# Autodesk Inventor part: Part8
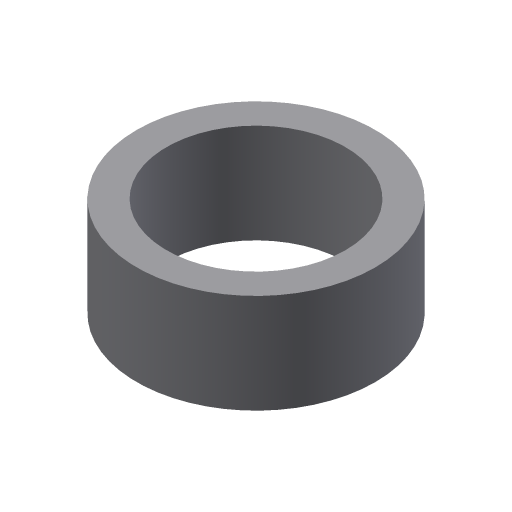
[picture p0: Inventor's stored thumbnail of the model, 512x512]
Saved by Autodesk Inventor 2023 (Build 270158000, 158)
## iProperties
Created: 2002-01
Part Number: Part8
Document SubType Name: Modeling
Designer: ***
Density: 1 g/cm^3
Material: Generic
Appearance: Default
Control State: 0
Master: False
Checked Out: False
Shininess: 77.0
Length Units: 11269
Angle Units: 11279
Time Units: 11290
Mass Units: 11283
Length Display Precision: 3
Angle Display Precision: 2
Density: 0.0
Volumn: 0.0
Area: 0.0
PropertySet Name: Model Information
Author: ***
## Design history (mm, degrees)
sketch "Sketch1"
  geometry: C1 r 30 at (0, 0); C2 r 22.5 at (0, 0)
  constraints: 2 centre point, 1 coincident
  dimensions: "d0" = 60 diameter of C1; "d1" = 45 diameter of C2
extrude "Extrusion1" new body sketch "Sketch1" distance "d2" = 25; taper "d3" = 0 deg
body "Solid1"
